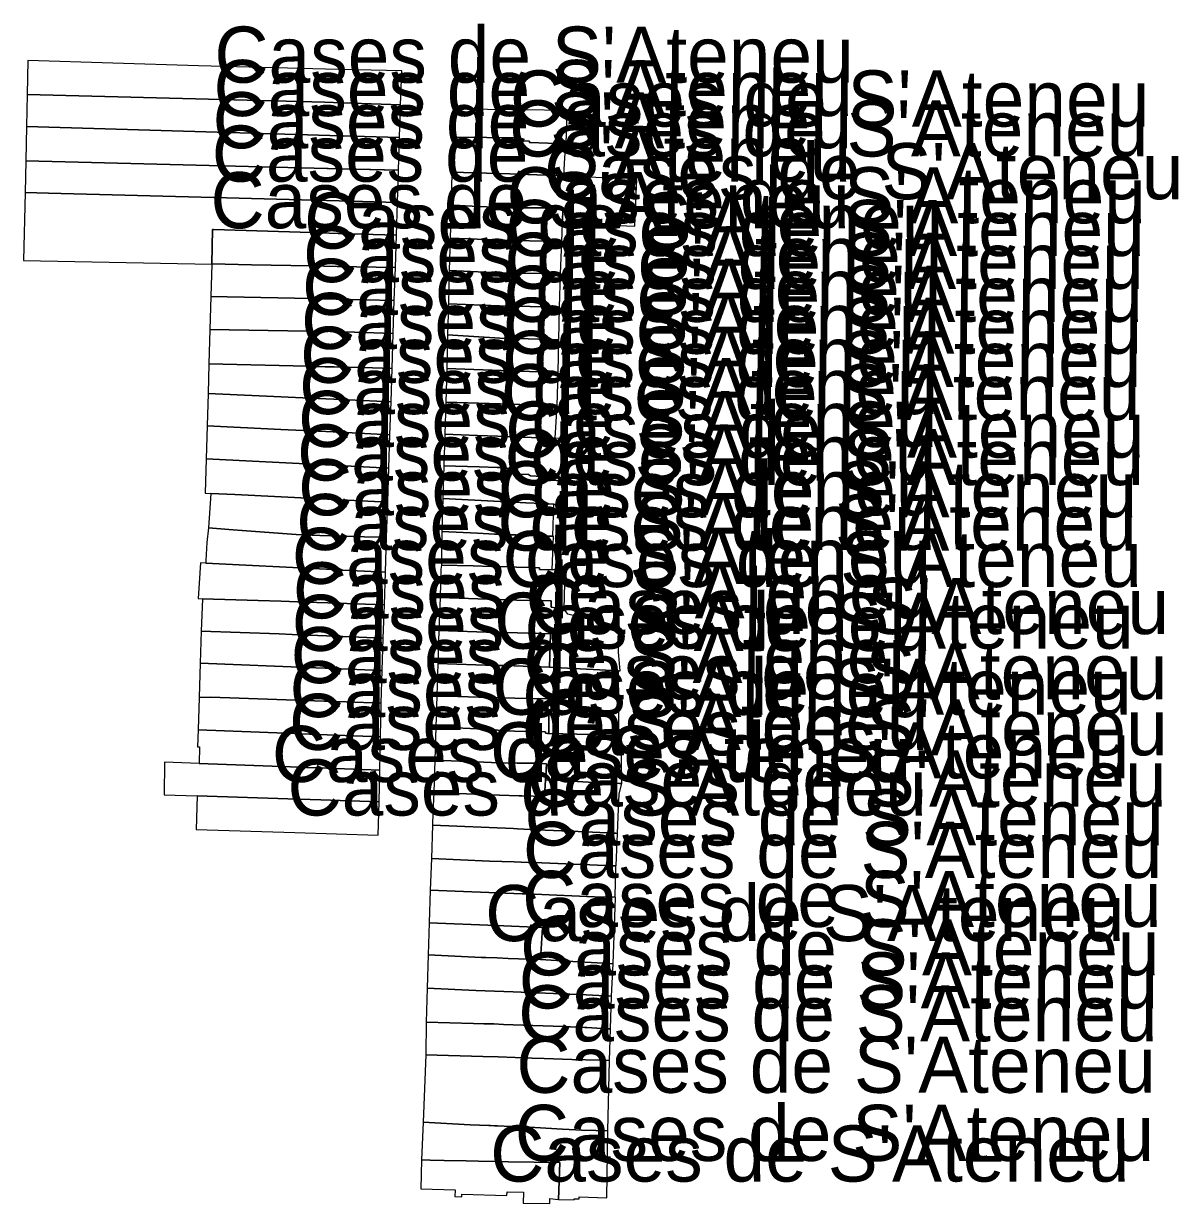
# Model space of a CAD drawing. Extents: x 599451 to 612034, y 4411179 to 4428219.
# Drawn here: x 607609 to 607856.2, y 4414565.9 to 4414818.3 of the extents above; entities that cross this region are included whole.
import ezdxf

# ---------------------------------------------------------------- set-up
doc = ezdxf.new("R2010")
doc.units = 0
doc.layers.add('Elements patrimonials', color=7, linetype='Continuous')

msp = doc.modelspace()

# ---------------------------------------------------------------- linework, layer by layer
at = {"layer": 'Elements patrimonials'}
for points in [[(607689.96, 4414808.23), (607673.67, 4414808.57), (607646.49, 4414809.32), (607628.1, 4414809.87), (607609.92, 4414810.41), (607609.77, 4414803.14), (607673.53, 4414801.52), (607677.23, 4414801.38), (607689.73, 4414800.95)], [(607609.62, 4414796.34), (607650.47, 4414795.11), (607677.02, 4414794.31), (607689.5, 4414793.93), (607689.73, 4414800.95), (607677.23, 4414801.38), (607673.53, 4414801.52), (607609.77, 4414803.14)], [(607725.36, 4414799.76), (607715.58, 4414799.9), (607701.06, 4414799.99), (607700.9, 4414794.02), (607715.43, 4414793.87), (607715.43, 4414793.86), (607715.42, 4414793.23), (607716.05, 4414793.22), (607717.32, 4414793.2), (607717.33, 4414793.2), (607717.32, 4414793.03), (607717.31, 4414792.86), (607717.32, 4414792.86), (607725.17, 4414792.6)], [(607689.5, 4414793.93), (607677.02, 4414794.31), (607650.47, 4414795.11), (607609.62, 4414796.34), (607609.47, 4414788.95), (607671.19, 4414787.4), (607676.8, 4414787.26), (607689.28, 4414786.95)], [(607724.9, 4414789.7), (607725.17, 4414792.6), (607717.32, 4414792.86), (607717.31, 4414792.86), (607717.32, 4414793.03), (607717.33, 4414793.2), (607717.32, 4414793.2), (607716.05, 4414793.22), (607715.42, 4414793.23), (607715.43, 4414793.86), (607715.43, 4414793.87), (607700.9, 4414794.02), (607700.7, 4414786.51), (607713.11, 4414786.21), (607724.68, 4414785.75)], [(607689.28, 4414786.95), (607671.19, 4414787.4), (607609.47, 4414788.95), (607609.33, 4414782.19), (607614.34, 4414782.06), (607652.46, 4414781.05), (607676.59, 4414780.41), (607689.05, 4414780.08), (607689.05, 4414780.07), (607689.06, 4414780.07)], [(607740.13, 4414781.9), (607740.3, 4414784.91), (607739.88, 4414784.93), (607739.87, 4414784.94), (607734.26, 4414785.23), (607724.68, 4414785.75), (607713.11, 4414786.21), (607700.7, 4414786.51), (607700.52, 4414779.5), (607712.62, 4414778.93), (607714.71, 4414778.9), (607724.48, 4414778.88), (607724.35, 4414775.63), (607726.67, 4414775.59), (607734.5, 4414775.22), (607739.89, 4414774.99)], [(607689.05, 4414780.07), (607689.05, 4414780.08), (607676.59, 4414780.41), (607652.46, 4414781.05), (607614.34, 4414782.06), (607609.33, 4414782.19), (607609.02, 4414767.66), (607649.29, 4414766.89), (607649.29, 4414766.9), (607649.29, 4414766.91), (607649.49, 4414774.24), (607649.49, 4414774.24), (607649.68, 4414774.24), (607670.59, 4414773.6), (607676.37, 4414773.41), (607688.83, 4414773.03)], [(607724.35, 4414775.63), (607724.48, 4414778.88), (607714.71, 4414778.9), (607712.62, 4414778.93), (607700.52, 4414779.5), (607700.33, 4414772.41), (607713.89, 4414771.92), (607724.2, 4414771.7)], [(607688.83, 4414773.03), (607676.37, 4414773.41), (607670.59, 4414773.6), (607649.68, 4414774.24), (607649.49, 4414774.24), (607649.49, 4414774.24), (607649.29, 4414766.91), (607649.29, 4414766.9), (607657.77, 4414766.73), (607670.43, 4414766.5), (607676.16, 4414766.38), (607688.6, 4414766.14)], [(607724.2, 4414771.7), (607713.89, 4414771.92), (607700.33, 4414772.41), (607700.14, 4414765.47), (607712.49, 4414764.95), (607715.99, 4414764.91), (607723.92, 4414764.78)], [(607688.6, 4414766.14), (607676.16, 4414766.38), (607670.43, 4414766.5), (607657.77, 4414766.73), (607649.29, 4414766.9), (607649.29, 4414766.89), (607649.09, 4414759.97), (607652.63, 4414759.89), (607670.62, 4414759.49), (607675.95, 4414759.37), (607688.37, 4414759.11)], [(607723.92, 4414764.78), (607715.99, 4414764.91), (607712.49, 4414764.95), (607700.14, 4414765.47), (607699.95, 4414758.35), (607710.86, 4414757.94), (607714.34, 4414757.84), (607723.72, 4414757.69)], [(607688.37, 4414759.11), (607675.95, 4414759.37), (607670.62, 4414759.49), (607652.63, 4414759.89), (607649.09, 4414759.97), (607648.9, 4414752.85), (607669.75, 4414752.52), (607675.73, 4414752.46), (607688.15, 4414752.05)], [(607723.72, 4414757.69), (607714.34, 4414757.84), (607710.86, 4414757.94), (607699.95, 4414758.35), (607699.78, 4414751.72), (607712.09, 4414750.99), (607714.12, 4414750.94), (607714.81, 4414750.92), (607723.57, 4414750.69)], [(607688.15, 4414752.05), (607675.73, 4414752.46), (607669.75, 4414752.52), (607648.9, 4414752.85), (607648.7, 4414745.51), (607669.74, 4414745.02), (607673.59, 4414744.92), (607675.49, 4414744.88), (607681.62, 4414744.73), (607687.9, 4414744.57)], [(607723.57, 4414750.69), (607714.81, 4414750.92), (607714.12, 4414750.94), (607712.09, 4414750.99), (607699.78, 4414751.72), (607699.59, 4414744.57), (607713.16, 4414744.05), (607723.48, 4414743.66)], [(607687.9, 4414744.57), (607681.62, 4414744.73), (607675.49, 4414744.88), (607673.59, 4414744.92), (607669.74, 4414745.02), (607648.7, 4414745.51), (607648.52, 4414739.18), (607670.39, 4414738.21), (607675.41, 4414737.98), (607687.67, 4414737.43)], [(607723.48, 4414743.66), (607713.16, 4414744.05), (607699.59, 4414744.57), (607699.39, 4414737.36), (607711.01, 4414736.95), (607715.24, 4414736.82), (607723.21, 4414736.6)], [(607687.67, 4414737.43), (607675.41, 4414737.98), (607670.39, 4414738.21), (607648.52, 4414739.18), (607648.33, 4414732.28), (607664.07, 4414731.5), (607675.32, 4414730.96), (607687.43, 4414730.38), (607687.44, 4414730.38)], [(607723.21, 4414736.6), (607715.24, 4414736.82), (607711.01, 4414736.95), (607699.39, 4414737.36), (607699.19, 4414730.5), (607706.18, 4414730.21), (607710.44, 4414730.03), (607713.57, 4414729.91), (607717.76, 4414729.78), (607722.83, 4414729.61)], [(607687.43, 4414730.38), (607675.32, 4414730.96), (607664.07, 4414731.5), (607648.33, 4414732.28), (607648.13, 4414725.18), (607675.08, 4414723.84), (607687.21, 4414723.24), (607687.21, 4414723.23), (607687.22, 4414723.23), (607687.44, 4414730.36), (607687.44, 4414730.37), (607687.44, 4414730.38)], [(607722.83, 4414729.61), (607717.76, 4414729.78), (607713.57, 4414729.91), (607710.44, 4414730.03), (607706.18, 4414730.21), (607699.19, 4414730.5), (607698.98, 4414723.69), (607706.52, 4414723.48), (607710.43, 4414723.37), (607711.25, 4414723.34), (607712.51, 4414723.25), (607714.3, 4414723.12), (607714.26, 4414721.9), (607717.09, 4414721.85), (607717.55, 4414721.57), (607719.87, 4414721.43), (607720.38, 4414720.8), (607724.86, 4414720.44), (607725.24, 4414729.51)], [(607687.21, 4414723.23), (607687.21, 4414723.24), (607675.08, 4414723.84), (607648.13, 4414725.18), (607647.92, 4414717.85), (607649.1, 4414717.79), (607654.26, 4414717.55), (607672.66, 4414716.65), (607686.97, 4414715.96)], [(607725.21, 4414720.42), (607724.86, 4414720.44), (607720.38, 4414720.8), (607719.87, 4414721.43), (607717.55, 4414721.57), (607717.09, 4414721.85), (607714.26, 4414721.9), (607714.3, 4414723.12), (607712.51, 4414723.25), (607711.25, 4414723.34), (607710.43, 4414723.37), (607706.52, 4414723.48), (607698.98, 4414723.69), (607698.77, 4414716.76), (607711.03, 4414716.07), (607712.99, 4414716.02), (607716.52, 4414715.82), (607720.04, 4414715.64), (607722.49, 4414715.55), (607725.04, 4414715.49)], [(607686.97, 4414715.96), (607672.66, 4414716.65), (607654.26, 4414717.55), (607649.1, 4414717.79), (607648.62, 4414710.43), (607652.94, 4414710.11), (607656.73, 4414709.83), (607667.38, 4414709.03), (607672.4, 4414708.78), (607681.95, 4414708.56), (607686.72, 4414708.45), (607686.73, 4414708.45)], [(607722.49, 4414715.55), (607720.04, 4414715.64), (607716.52, 4414715.82), (607712.99, 4414716.02), (607711.03, 4414716.07), (607698.77, 4414716.76), (607698.55, 4414709.7), (607706.2, 4414709.32), (607709.82, 4414709.13), (607710.82, 4414709.08), (607712.19, 4414709.03), (607712.6, 4414709.01), (607713.3, 4414708.99), (607714.49, 4414708.95), (607715.7, 4414708.91), (607718.85, 4414708.79), (607718.87, 4414708.79), (607719.85, 4414708.75), (607721.43, 4414708.69), (607722.28, 4414708.65)], [(607686.72, 4414708.45), (607681.95, 4414708.56), (607672.4, 4414708.78), (607667.38, 4414709.03), (607656.73, 4414709.83), (607652.94, 4414710.11), (607648.62, 4414710.43), (607648.27, 4414707.34), (607648.05, 4414703.47), (607648.05, 4414702.92), (607673.76, 4414701.62), (607675.89, 4414701.5), (607686.48, 4414700.97)], [(607722.48, 4414708.64), (607722.28, 4414708.65), (607721.43, 4414708.69), (607719.85, 4414708.75), (607718.87, 4414708.79), (607718.85, 4414708.79), (607715.7, 4414708.91), (607714.49, 4414708.95), (607713.3, 4414708.99), (607712.6, 4414709.01), (607712.19, 4414709.03), (607710.82, 4414709.08), (607709.82, 4414709.13), (607706.2, 4414709.32), (607698.55, 4414709.7), (607698.44, 4414702.5), (607705.22, 4414702.31), (607709.18, 4414702.19), (607712.91, 4414702.08), (607714.56, 4414702.03), (607717.7, 4414701.94), (607719.42, 4414701.89), (607719.42, 4414701.52), (607722.16, 4414701.47)], [(607686.48, 4414700.97), (607675.89, 4414701.5), (607673.76, 4414701.62), (607648.05, 4414702.92), (607646.91, 4414702.94), (607646.92, 4414702.93), (607646.41, 4414695.32), (607647.29, 4414695.27), (607659.23, 4414694.89), (607664.12, 4414694.73), (607669.43, 4414694.55), (607674.13, 4414694.39), (607686.26, 4414693.99)], [(607722.16, 4414701.47), (607719.42, 4414701.52), (607719.42, 4414701.89), (607717.7, 4414701.94), (607714.56, 4414702.03), (607712.91, 4414702.08), (607709.18, 4414702.19), (607705.22, 4414702.31), (607698.44, 4414702.5), (607698.33, 4414701.61), (607698.16, 4414695.58), (607710.34, 4414695.12), (607714.53, 4414695.01), (607721.96, 4414694.85), (607721.95, 4414693.46), (607724.73, 4414693.05), (607724.93, 4414701.42), (607724.67, 4414701.44)], [(607686.26, 4414693.99), (607674.13, 4414694.39), (607669.43, 4414694.55), (607664.12, 4414694.73), (607659.23, 4414694.89), (607647.29, 4414695.27), (607647.06, 4414688.35), (607663.7, 4414687.75), (607666.53, 4414687.64), (607673.84, 4414687.34), (607686.02, 4414686.88)], [(607736.35, 4414683.83), (607736.3, 4414687.15), (607736.56, 4414689.12), (607731.41, 4414690.58), (607725.49, 4414691.99), (607724.73, 4414693.05), (607721.95, 4414693.46), (607721.96, 4414694.85), (607714.53, 4414695.01), (607710.34, 4414695.12), (607698.16, 4414695.58), (607697.93, 4414688.52), (607710.12, 4414688.09), (607712.41, 4414688.06), (607719.39, 4414687.88), (607721.83, 4414687.79), (607721.61, 4414680.65), (607724.06, 4414680.53), (607736.39, 4414679.89), (607736.75, 4414679.87)], [(607686.02, 4414686.88), (607673.84, 4414687.34), (607666.53, 4414687.64), (607663.7, 4414687.75), (607647.06, 4414688.35), (607646.83, 4414681.52), (607671.54, 4414680.5), (607673.54, 4414680.43), (607685.41, 4414679.93), (607685.8, 4414679.91)], [(607721.83, 4414687.79), (607719.39, 4414687.88), (607712.41, 4414688.06), (607710.12, 4414688.09), (607697.93, 4414688.52), (607697.72, 4414681.4), (607709.92, 4414681), (607712.14, 4414680.99), (607721.6, 4414680.65), (607721.61, 4414680.65)], [(607685.8, 4414679.91), (607685.41, 4414679.93), (607673.54, 4414680.43), (607671.54, 4414680.5), (607646.83, 4414681.52), (607646.59, 4414674.18), (607649.09, 4414674.2), (607671.29, 4414673.43), (607673.39, 4414673.36), (607678.04, 4414673.21), (607685.57, 4414672.94)], [(607736.45, 4414668.82), (607736.43, 4414672.65), (607736.39, 4414679.89), (607724.06, 4414680.53), (607721.61, 4414680.65), (607721.6, 4414680.65), (607712.14, 4414680.99), (607709.92, 4414681), (607697.72, 4414681.4), (607697.49, 4414674.5), (607710.91, 4414674.07), (607717.45, 4414673.94), (607721.3, 4414673.86), (607721.15, 4414670.45), (607721.48, 4414670.43), (607721.44, 4414667.11), (607721.43, 4414666.48), (607736.47, 4414666.07)], [(607685.57, 4414672.94), (607678.04, 4414673.21), (607673.39, 4414673.36), (607671.29, 4414673.43), (607649.09, 4414674.2), (607646.59, 4414674.18), (607646.36, 4414667.27), (607667.04, 4414666.44), (607670.24, 4414666.31), (607685.41, 4414665.71)], [(607721.43, 4414666.48), (607721.44, 4414667.11), (607721.48, 4414670.43), (607721.15, 4414670.45), (607721.3, 4414673.86), (607717.45, 4414673.94), (607710.91, 4414674.07), (607697.49, 4414674.5), (607697.27, 4414667.83), (607701.51, 4414667.65), (607704.6, 4414667.52), (607707.49, 4414667.4), (607709.45, 4414667.31), (607711.57, 4414667.06), (607714.09, 4414666.98), (607716.68, 4414666.9), (607720.75, 4414666.82), (607720.74, 4414666.5), (607721.16, 4414666.45), (607721.4, 4414666.42)], [(607685.41, 4414665.71), (607670.24, 4414666.31), (607667.04, 4414666.44), (607646.36, 4414667.27), (607646.28, 4414663.59), (607646.69, 4414663.6), (607646.59, 4414660.06), (607666.13, 4414659.35), (607669.6, 4414659.21), (607672.11, 4414659.11), (607685.25, 4414658.63)], [(607721.16, 4414666.45), (607720.74, 4414666.5), (607720.75, 4414666.82), (607716.68, 4414666.9), (607714.09, 4414666.98), (607711.57, 4414667.06), (607709.45, 4414667.31), (607707.49, 4414667.4), (607704.6, 4414667.52), (607701.51, 4414667.65), (607697.27, 4414667.83), (607697.03, 4414660.75), (607705.83, 4414660.36), (607710.9, 4414660.16), (607714.69, 4414660.12), (607718.38, 4414660.09), (607720.93, 4414660), (607720.9, 4414658.86), (607720.9, 4414658.57), (607720.87, 4414658.24), (607720.74, 4414656.56), (607722.91, 4414656.46), (607731.1, 4414655.99), (607734.73, 4414655.84), (607736.58, 4414655.77), (607737.09, 4414655.75), (607736.92, 4414666.05), (607736.47, 4414666.07), (607721.43, 4414666.48), (607721.4, 4414666.42)], [(607720.74, 4414656.56), (607720.87, 4414658.24), (607720.9, 4414658.57), (607720.9, 4414658.86), (607720.93, 4414660), (607718.38, 4414660.09), (607714.69, 4414660.12), (607710.9, 4414660.16), (607705.83, 4414660.36), (607697.03, 4414660.75), (607696.8, 4414653.81), (607709, 4414653.36), (607710.9, 4414653.29), (607715.09, 4414653.15), (607715.68, 4414653.13), (607720.54, 4414652.97)], [(607646.59, 4414660.06), (607639.2, 4414660.34), (607639.1, 4414653.37), (607646.19, 4414653.13), (607665.58, 4414652.48), (607670.34, 4414652.31), (607672.68, 4414652.23), (607685.1, 4414651.81), (607685.25, 4414658.63), (607672.11, 4414659.11), (607669.6, 4414659.21), (607666.13, 4414659.35)], [(607736.5, 4414653.57), (607737.09, 4414655.75), (607736.58, 4414655.77), (607734.73, 4414655.84), (607731.1, 4414655.99), (607722.91, 4414656.46), (607720.74, 4414656.56), (607720.54, 4414652.97), (607715.68, 4414653.13), (607715.09, 4414653.15), (607710.9, 4414653.29), (607709, 4414653.36), (607696.8, 4414653.81), (607696.65, 4414649.51), (607696.57, 4414646.88), (607713.89, 4414646.11), (607714.72, 4414646.07), (607718.88, 4414645.88), (607718.89, 4414645.88), (607722.44, 4414645.72), (607727.7, 4414645.46), (607727.7, 4414645.46), (607735.44, 4414645.12), (607735.8, 4414645.11), (607736.16, 4414645.09), (607736.3, 4414648.65)], [(607685.1, 4414651.81), (607672.68, 4414652.23), (607670.34, 4414652.31), (607665.58, 4414652.48), (607646.19, 4414653.13), (607645.93, 4414645.93), (607667.09, 4414645.26), (607684.95, 4414644.68)], [(607736.16, 4414645.09), (607735.8, 4414645.11), (607735.44, 4414645.12), (607727.7, 4414645.46), (607727.7, 4414645.46), (607722.44, 4414645.72), (607718.89, 4414645.88), (607718.88, 4414645.88), (607714.72, 4414646.07), (607713.89, 4414646.11), (607696.57, 4414646.88), (607696.3, 4414639.7), (607708.78, 4414639.16), (607714, 4414639.01), (607717.05, 4414638.89), (607719.98, 4414638.78), (607730.26, 4414638.36), (607735.11, 4414638.16), (607735.15, 4414638.15), (607735.16, 4414638.16), (607735.78, 4414638.13), (607735.84, 4414638.13)], [(607735.11, 4414638.16), (607730.26, 4414638.36), (607719.98, 4414638.78), (607717.05, 4414638.89), (607714, 4414639.01), (607708.78, 4414639.16), (607696.3, 4414639.7), (607696.05, 4414632.95), (607715.76, 4414632.19), (607717.45, 4414632.13), (607718.31, 4414632.09), (607731.22, 4414631.51), (607735.66, 4414631.41), (607735.78, 4414638.13), (607735.16, 4414638.16), (607735.15, 4414638.15)], [(607735.72, 4414631.31), (607735.72, 4414631.41), (607735.66, 4414631.41), (607731.22, 4414631.51), (607718.31, 4414632.09), (607717.45, 4414632.13), (607715.76, 4414632.19), (607696.05, 4414632.95), (607695.8, 4414625.97), (607710.2, 4414625.36), (607720.07, 4414624.94), (607719.69, 4414618.1), (607726.6, 4414617.7), (607731.83, 4414617.4), (607735.25, 4414617.2)], [(607720.07, 4414624.94), (607710.2, 4414625.36), (607695.8, 4414625.97), (607695.59, 4414619.13), (607707.01, 4414618.57), (607707.94, 4414618.52), (607710.41, 4414618.43), (607712.73, 4414618.35), (607717.15, 4414618.19), (607719.69, 4414618.1)], [(607735.25, 4414617.2), (607731.83, 4414617.4), (607726.6, 4414617.7), (607719.69, 4414618.1), (607717.15, 4414618.19), (607712.73, 4414618.35), (607710.41, 4414618.43), (607707.94, 4414618.52), (607707.01, 4414618.57), (607695.59, 4414619.13), (607695.38, 4414611.98), (607705.79, 4414611.51), (607705.8, 4414611.51), (607713.85, 4414611.17), (607720.71, 4414610.88), (607729.41, 4414610.52), (607734.87, 4414610.29)], [(607734.87, 4414610.29), (607729.41, 4414610.52), (607720.71, 4414610.88), (607713.85, 4414611.17), (607705.8, 4414611.51), (607705.79, 4414611.51), (607695.38, 4414611.98), (607695.16, 4414604.72), (607705.29, 4414604.44), (607705.3, 4414604.43), (607707.52, 4414604.37), (607709.68, 4414604.32), (607711.73, 4414604.23), (607718.05, 4414603.99), (607724.59, 4414603.75), (607724.62, 4414603.75), (607729.17, 4414603.58), (607729.57, 4414603.56), (607732.82, 4414603.38), (607734.17, 4414603.31), (607734.68, 4414603.28)], [(607734.68, 4414603.28), (607734.17, 4414603.31), (607732.82, 4414603.38), (607729.57, 4414603.56), (607729.17, 4414603.58), (607724.62, 4414603.75), (607724.59, 4414603.75), (607718.05, 4414603.99), (607711.73, 4414604.23), (607709.68, 4414604.32), (607707.52, 4414604.37), (607705.3, 4414604.43), (607705.29, 4414604.44), (607695.16, 4414604.72), (607695.13, 4414597.74), (607707.32, 4414597.37), (607710.6, 4414597.26), (607717.9, 4414597.03), (607720.46, 4414596.94), (607726.38, 4414596.75), (607732.27, 4414596.55), (607734.46, 4414596.48)], [(607734.46, 4414596.48), (607732.27, 4414596.55), (607726.38, 4414596.75), (607720.46, 4414596.94), (607717.9, 4414597.03), (607710.6, 4414597.26), (607707.32, 4414597.37), (607695.13, 4414597.74), (607694.55, 4414583.31), (607704.59, 4414582.77), (607708.59, 4414582.6), (607708.95, 4414582.59), (607709.85, 4414582.55), (607710.43, 4414582.53), (607710.46, 4414582.52), (607714.65, 4414582.34), (607715.18, 4414582.32), (607718.43, 4414582.14), (607724.39, 4414581.8), (607724.4, 4414581.8), (607727.21, 4414581.65), (607728.44, 4414581.58), (607731.53, 4414581.51), (607734.11, 4414581.45)], [(607734.11, 4414581.45), (607731.53, 4414581.51), (607728.44, 4414581.58), (607727.21, 4414581.65), (607724.4, 4414581.8), (607724.39, 4414581.8), (607718.43, 4414582.14), (607715.18, 4414582.32), (607714.65, 4414582.34), (607710.46, 4414582.52), (607710.43, 4414582.53), (607709.85, 4414582.55), (607708.95, 4414582.59), (607708.59, 4414582.6), (607704.59, 4414582.77), (607694.55, 4414583.31), (607694.21, 4414575.26), (607696.05, 4414575.21), (607699.03, 4414575.14), (607703.78, 4414575.01), (607706.39, 4414574.94), (607711.34, 4414574.88), (607712.74, 4414574.86), (607723.79, 4414574.65), (607723.54, 4414566.79), (607726.85, 4414566.73), (607726.86, 4414566.91), (607727.91, 4414566.89), (607727.94, 4414567.34), (607733.9, 4414567.13)], [(607723.79, 4414574.65), (607712.74, 4414574.86), (607711.34, 4414574.88), (607706.39, 4414574.94), (607703.78, 4414575.01), (607699.03, 4414575.14), (607696.05, 4414575.21), (607694.21, 4414575.26), (607694.02, 4414569.08), (607701.38, 4414568.86), (607701.31, 4414567.38), (607702.8, 4414567.34), (607702.83, 4414567.91), (607712.49, 4414567.59), (607712.52, 4414568.39), (607716.03, 4414568.34), (607715.98, 4414565.98), (607721.66, 4414565.93), (607721.67, 4414566.97), (607723.54, 4414566.79)]]:
    msp.add_lwpolyline(points, close=True, dxfattribs=at)

# ---------------------------------------------------------------- texts
for p in [(607649.86, 4414805.68), (607649.67, 4414798.54), (607713.13, 4414796.3), (607649.48, 4414791.65), (607712.93, 4414789.89), (607649.3, 4414784.51), (607720.41, 4414780.75), (607649.03, 4414774.54), (607712.4, 4414775.6), (607669.06, 4414770.19), (607712.17, 4414768.6), (607668.84, 4414763.01), (607711.93, 4414761.58), (607668.63, 4414756.01), (607711.75, 4414754.52), (607668.42, 4414748.71), (607711.58, 4414747.69), (607668.21, 4414741.47), (607711.43, 4414740.59), (607668, 4414734.78), (607711.2, 4414733.49), (607667.78, 4414727.75), (607712.11, 4414725.47), (607667.56, 4414720.57), (607711.99, 4414719.59), (607667.79, 4414713.12), (607710.52, 4414712.71), (607667.38, 4414705.7), (607710.46, 4414705.59), (607666.44, 4414698.47), (607711.54, 4414697.78), (607666.66, 4414691.08), (607717.34, 4414687.73), (607666.42, 4414684.13), (607709.77, 4414684.59), (607666.19, 4414677.23), (607716.98, 4414673.74), (607709.37, 4414670.46), (607665.96, 4414669.96), (607665.84, 4414662.95), (607717.06, 4414661.79), (607662.17, 4414656.08), (607708.86, 4414656.86), (607716.83, 4414650.83), (607665.51, 4414648.91), (607716.23, 4414642.5), (607715.91, 4414635.56), (607715.76, 4414625.07), (607707.83, 4414622.04), (607715.31, 4414614.71), (607715.01, 4414607.63), (607714.9, 4414600.6), (607714.5, 4414589.59), (607714.16, 4414575.02), (607708.9, 4414570.6)]:
    msp.add_text("Cases de S'Ateneu", height=12, dxfattribs=at).set_placement(p)

doc.saveas('drawing.dxf')
